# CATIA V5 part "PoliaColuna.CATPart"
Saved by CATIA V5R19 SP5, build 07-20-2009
Part number: PeçaVeioPotenciometro.1
Bounding box of the stored display mesh (mm): x -4 to 4, y -27.464 to 27.464, z -27.464 to 27.464
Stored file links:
  Z:\UA\ATLAS\atlascar\ServoPiloto\dir\suportePotenciometro\V2\PoliaColuna.CATPart
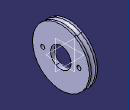
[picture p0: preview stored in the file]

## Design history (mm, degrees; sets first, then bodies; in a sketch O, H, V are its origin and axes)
Body1 (main body)
  Sketch1 on zx-plane, origin (0, 0, 0), H (-1, 0, 0), V (0, 0, 1)
    line L1 (-4, 10) -> (0, 10)
    point P3 (-4, 27.5)
    point P4 (-4, 27.5)
    line L2 (-4, 10) -> (-4, 27.5)
    point P5 (-2, 27.5)
    arc A1 centre (0, 27.5) radius 2 from (-2, 27.5) to (2, 27.5) ccw
    point P7 (0, 27.5)
    line L3 (0, 10) -> (0, 22.5)
    line L4 (0, 22.5) -> (4, 22.5)
    line L5 (2, 27.5) -> (4, 27.5)
    line L6 (4, 22.5) -> (4, 27.5)
    line L7 (-4, 27.5) -> (-2, 27.5)
    point P11 (-2, 27.5)
    distance H L1 = 10
    length L1 = 4
    radius A1 = 2
    distance H P7 = 27.5
    distance L4 H = 22.5
    length L4 = 4
    horizontal: L1 H, L4 H, L5 H
    vertical: L2 V, L3 V, L6 V
    coincidence: L3 V, P11 A1, L7 L5, P5 P11, P7 L5, P4 P3
    equidistance: L2 L6 P7
  Shaft1: profile Sketch1, axis Sketch1.H, angle 360
  Sketch2 on face of Shaft1 from Sketch1.L3, origin (0, 0, 0), H (0, -1, 0), V (0, 0, 1)
    construction circle A1 centre (0, 0) radius 17.5
    circle A2 centre (17.5, 0) radius 2
    point P1 (17.5, 0)
    circle A3 centre (-17.5, 0) radius 2
    point P2 (-17.5, 0)
    radius A1 = 17.5
    radius A3 = 2
    radius A2 = 2
    coincidence: P2 A1, P1 A1
  Pocket1: profile Sketch2, direction (1, 0, 0), through (limit type 3)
